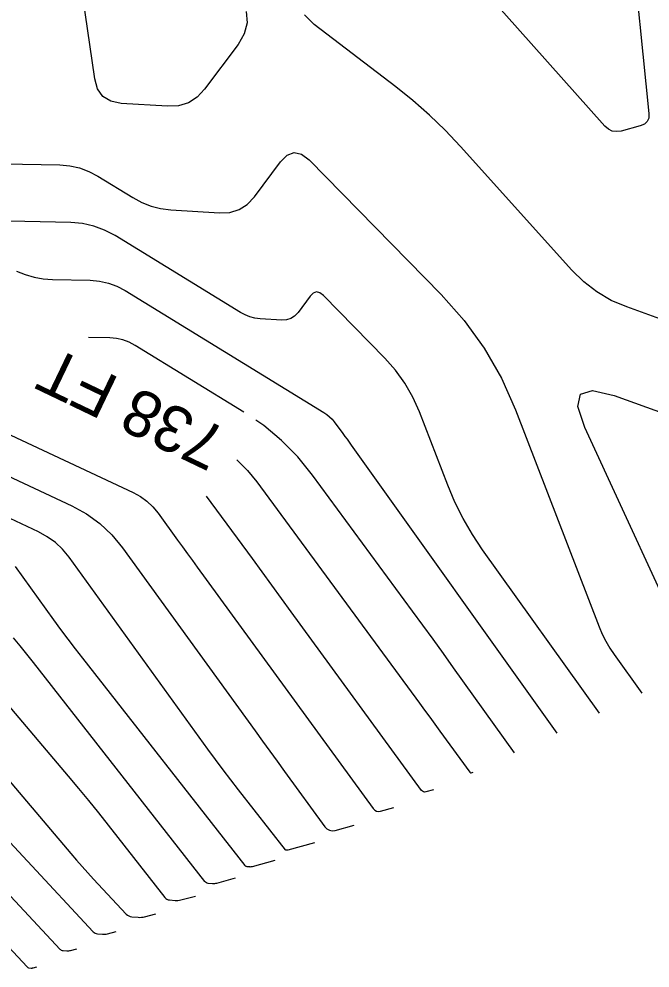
# Model space of a CAD drawing. Extents: x 1354696 to 1366163, y 660729 to 670380.
# Drawn here: x 1361676.3 to 1361758.6, y 664209.8 to 664333.6 of the extents above; entities that cross this region are included whole.
import ezdxf

# ---------------------------------------------------------------- set-up
doc = ezdxf.new("R2010")
doc.units = 0
doc.layers.add('R_Contour Annot', color=7, linetype='Continuous')
doc.layers.add('R_Contours', color=7, linetype='Continuous')

msp = doc.modelspace()

# ---------------------------------------------------------------- linework, layer by layer
at = {"layer": 'R_Contours'}
for points in [[(1361705.99, 664334.58), (1361706.08, 664333.1), (1361705.72, 664331.66), (1361704.91, 664330.26), (1361700.55, 664324.42), (1361699.56, 664323.38), (1361698.43, 664322.66), (1361697.15, 664322.26), (1361695.71, 664322.2), (1361689.67, 664322.59), (1361688.33, 664322.87), (1361687.3, 664323.49), (1361686.6, 664324.46), (1361686.22, 664325.78), (1361682.18, 664353.56)], [(1361756.08, 664344.96), (1361758.49, 664321.26), (1361758.47, 664320.67), (1361758.28, 664320.21), (1361757.91, 664319.86), (1361757.37, 664319.64), (1361754.86, 664318.98), (1361754.26, 664318.9), (1361753.7, 664318.98), (1361753.2, 664319.22), (1361752.74, 664319.62), (1361732.09, 664342.81)], [(1361764.21, 664292.94), (1361755.59, 664296.04), (1361753.58, 664296.9), (1361751.72, 664297.99), (1361750.01, 664299.3), (1361748.45, 664300.83), (1361733.9, 664316.98), (1361731.93, 664319.07), (1361729.87, 664321.06), (1361727.72, 664322.95), (1361725.47, 664324.75), (1361714.83, 664332.86), (1361713.59, 664334.11)], [(1361669.43, 664314.79), (1361681.65, 664314.55), (1361682.97, 664314.44), (1361684.23, 664314.16), (1361685.45, 664313.71), (1361686.62, 664313.09), (1361691.18, 664310.29), (1361692.35, 664309.67), (1361693.56, 664309.2), (1361694.82, 664308.88), (1361696.14, 664308.72), (1361702.48, 664308.3), (1361703.84, 664308.37), (1361705.05, 664308.74), (1361706.12, 664309.42), (1361707.04, 664310.41), (1361710.46, 664314.98), (1361711.33, 664315.85), (1361712.24, 664316.18), (1361713.19, 664315.97), (1361714.17, 664315.23), (1361731.39, 664297.68), (1361734.4, 664294.29), (1361737.02, 664290.65), (1361739.25, 664286.75), (1361741.09, 664282.61), (1361752.01, 664254.32), (1361752.41, 664253.37), (1361752.87, 664252.45), (1361753.38, 664251.56), (1361753.95, 664250.71), (1361757.56, 664245.67)], [(1361752.03, 664243.07), (1361736.81, 664264.37), (1361735.47, 664266.37), (1361734.27, 664268.45), (1361733.2, 664270.59), (1361732.26, 664272.81), (1361728.57, 664282.37), (1361727.71, 664284.29), (1361726.68, 664286.11), (1361725.46, 664287.8), (1361724.06, 664289.38), (1361716.04, 664297.54), (1361715.59, 664297.89), (1361715.15, 664297.99), (1361714.72, 664297.84), (1361714.32, 664297.43), (1361712.73, 664295.3), (1361712.29, 664294.84), (1361711.8, 664294.53), (1361711.23, 664294.35), (1361710.6, 664294.32), (1361707.79, 664294.51), (1361707.11, 664294.59), (1361706.46, 664294.76), (1361705.83, 664295), (1361705.23, 664295.32), (1361688.87, 664305.35), (1361687.51, 664306.07), (1361686.09, 664306.59), (1361684.62, 664306.92), (1361683.09, 664307.04), (1361675.11, 664307.21)], [(1361676.02, 664300.71), (1361677.15, 664300.25), (1361678.31, 664299.92), (1361679.5, 664299.71), (1361680.71, 664299.62), (1361685.63, 664299.52), (1361686.84, 664299.42), (1361688, 664299.16), (1361689.11, 664298.75), (1361690.18, 664298.18), (1361716.11, 664282.29), (1361716.49, 664282.03), (1361716.85, 664281.73), (1361717.17, 664281.41), (1361717.46, 664281.04), (1361718.57, 664279.53), (1361718.85, 664279.16), (1361719.13, 664278.78), (1361719.4, 664278.4), (1361719.67, 664278.02), (1361746.5, 664240.47)], [(1361705.68, 664282.33), (1361691.49, 664291.02), (1361690.71, 664291.43), (1361689.9, 664291.73), (1361689.05, 664291.92), (1361688.17, 664292), (1361685.39, 664292.05)], [(1361764.61, 664248.96), (1361750.13, 664280.32), (1361749.22, 664283.07), (1361749.56, 664284.68), (1361751.13, 664285.15), (1361753.95, 664284.48), (1361767.69, 664279.54)], [(1361740.97, 664237.88), (1361733.02, 664249), (1361731.69, 664250.86), (1361730.35, 664252.7), (1361729.01, 664254.55), (1361727.67, 664256.39), (1361714.64, 664274.11), (1361712.71, 664276.48), (1361710.58, 664278.64), (1361708.26, 664280.57), (1361707.24, 664281.26)], [(1361673.84, 664279.96), (1361691.24, 664271.83), (1361692.18, 664271.31), (1361693.03, 664270.7), (1361693.8, 664269.97), (1361694.48, 664269.14), (1361697.03, 664265.62), (1361697.67, 664264.74), (1361698.31, 664263.86), (1361698.95, 664262.98), (1361699.59, 664262.1), (1361722.54, 664230.63), (1361722.73, 664230.42), (1361722.95, 664230.3), (1361723.2, 664230.26), (1361723.48, 664230.3), (1361725.22, 664230.77)], [(1361704.77, 664276.1), (1361704.81, 664276.07), (1361706.15, 664274.71), (1361707.36, 664273.22), (1361728.57, 664244.37), (1361729.23, 664243.47), (1361729.9, 664242.56), (1361730.56, 664241.65), (1361731.23, 664240.74), (1361735.15, 664235.36), (1361735.18, 664235.33), (1361735.22, 664235.31), (1361735.25, 664235.31), (1361735.3, 664235.31), (1361735.57, 664235.38)], [(1361673.39, 664274.72), (1361683.24, 664270.12), (1361685.16, 664269.08), (1361686.9, 664267.82), (1361688.46, 664266.34), (1361689.85, 664264.65), (1361707.14, 664240.75), (1361708.1, 664239.43), (1361709.05, 664238.11), (1361710.01, 664236.79), (1361710.97, 664235.47), (1361716.23, 664228.26), (1361716.51, 664227.97), (1361716.82, 664227.8), (1361717.17, 664227.74), (1361717.57, 664227.79), (1361720.05, 664228.46)], [(1361730.39, 664233.08), (1361729.39, 664232.8), (1361729.23, 664232.78), (1361729.08, 664232.81), (1361728.96, 664232.88), (1361728.85, 664232.99), (1361711.85, 664256.29), (1361710.59, 664258.03), (1361709.32, 664259.76), (1361708.05, 664261.5), (1361706.78, 664263.23), (1361700.8, 664271.36)], [(1361714.87, 664226.15), (1361711.4, 664225.21), (1361711.37, 664225.21), (1361711.35, 664225.2), (1361711.32, 664225.2), (1361711.29, 664225.2), (1361711.17, 664225.21), (1361711.15, 664225.22), (1361711.12, 664225.23), (1361711.1, 664225.24), (1361711.08, 664225.26), (1361704.98, 664233.06), (1361703.96, 664234.38), (1361702.96, 664235.7), (1361701.96, 664237.03), (1361700.98, 664238.37), (1361682.87, 664263.42), (1361682.03, 664264.44), (1361681.09, 664265.33), (1361680.03, 664266.08), (1361678.88, 664266.72), (1361672.94, 664269.49)], [(1361709.7, 664223.84), (1361706.75, 664223.05), (1361706.67, 664223.03), (1361706.59, 664223.02), (1361706.51, 664223.01), (1361706.43, 664223.02), (1361706.1, 664223.04), (1361706.02, 664223.06), (1361705.95, 664223.09), (1361705.89, 664223.13), (1361705.84, 664223.19), (1361684.68, 664250.23), (1361683.71, 664251.47), (1361682.76, 664252.73), (1361681.82, 664253.99), (1361680.89, 664255.26), (1361675.88, 664262.18)], [(1361666.49, 664254.01), (1361682.77, 664234.84), (1361684.1, 664233.26), (1361685.41, 664231.67), (1361686.7, 664230.07), (1361687.97, 664228.46), (1361695.35, 664219.03), (1361695.48, 664218.9), (1361695.62, 664218.8), (1361695.78, 664218.74), (1361695.96, 664218.71), (1361696.7, 664218.64), (1361696.89, 664218.64), (1361697.08, 664218.65), (1361697.26, 664218.67), (1361697.44, 664218.71), (1361699.35, 664219.23)], [(1361659.23, 664252.88), (1361683.12, 664224.76), (1361683.84, 664223.92), (1361684.58, 664223.08), (1361685.32, 664222.26), (1361686.08, 664221.44), (1361690.34, 664216.87), (1361690.49, 664216.73), (1361690.66, 664216.63), (1361690.85, 664216.56), (1361691.05, 664216.52), (1361691.9, 664216.45), (1361692.11, 664216.44), (1361692.32, 664216.45), (1361692.53, 664216.48), (1361692.73, 664216.53), (1361694.18, 664216.92)], [(1361704.53, 664221.54), (1361702.09, 664220.88), (1361701.96, 664220.85), (1361701.83, 664220.83), (1361701.7, 664220.83), (1361701.57, 664220.83), (1361701.03, 664220.88), (1361700.9, 664220.9), (1361700.79, 664220.94), (1361700.68, 664221.02), (1361700.6, 664221.11), (1361678.24, 664249.67), (1361677.38, 664250.76), (1361676.52, 664251.83), (1361675.64, 664252.89)], [(1361660.27, 664242.19), (1361686.03, 664214.57), (1361686.15, 664214.46), (1361686.28, 664214.38), (1361686.42, 664214.33), (1361686.58, 664214.3), (1361687.24, 664214.25), (1361687.4, 664214.24), (1361687.56, 664214.25), (1361687.72, 664214.27), (1361687.88, 664214.31), (1361689.01, 664214.61)], [(1361683.84, 664212.3), (1361683.04, 664212.09), (1361682.92, 664212.06), (1361682.81, 664212.05), (1361682.69, 664212.04), (1361682.58, 664212.05), (1361682.11, 664212.08), (1361682, 664212.1), (1361681.9, 664212.14), (1361681.8, 664212.2), (1361681.72, 664212.27), (1361655.9, 664239.95)], [(1361665.13, 664223.14), (1361677.41, 664209.98), (1361677.46, 664209.93), (1361677.51, 664209.9), (1361677.57, 664209.88), (1361677.64, 664209.86), (1361677.92, 664209.84), (1361677.98, 664209.84), (1361678.05, 664209.84), (1361678.12, 664209.85), (1361678.19, 664209.87), (1361678.66, 664209.99)]]:
    msp.add_lwpolyline(points, dxfattribs=at)

# ---------------------------------------------------------------- texts
at = {"layer": 'R_Contour Annot'}
msp.add_text('738 FT', height=6, rotation=154.3831, dxfattribs=at).set_placement((1361703.74, 664279.93))

doc.saveas('drawing.dxf')
